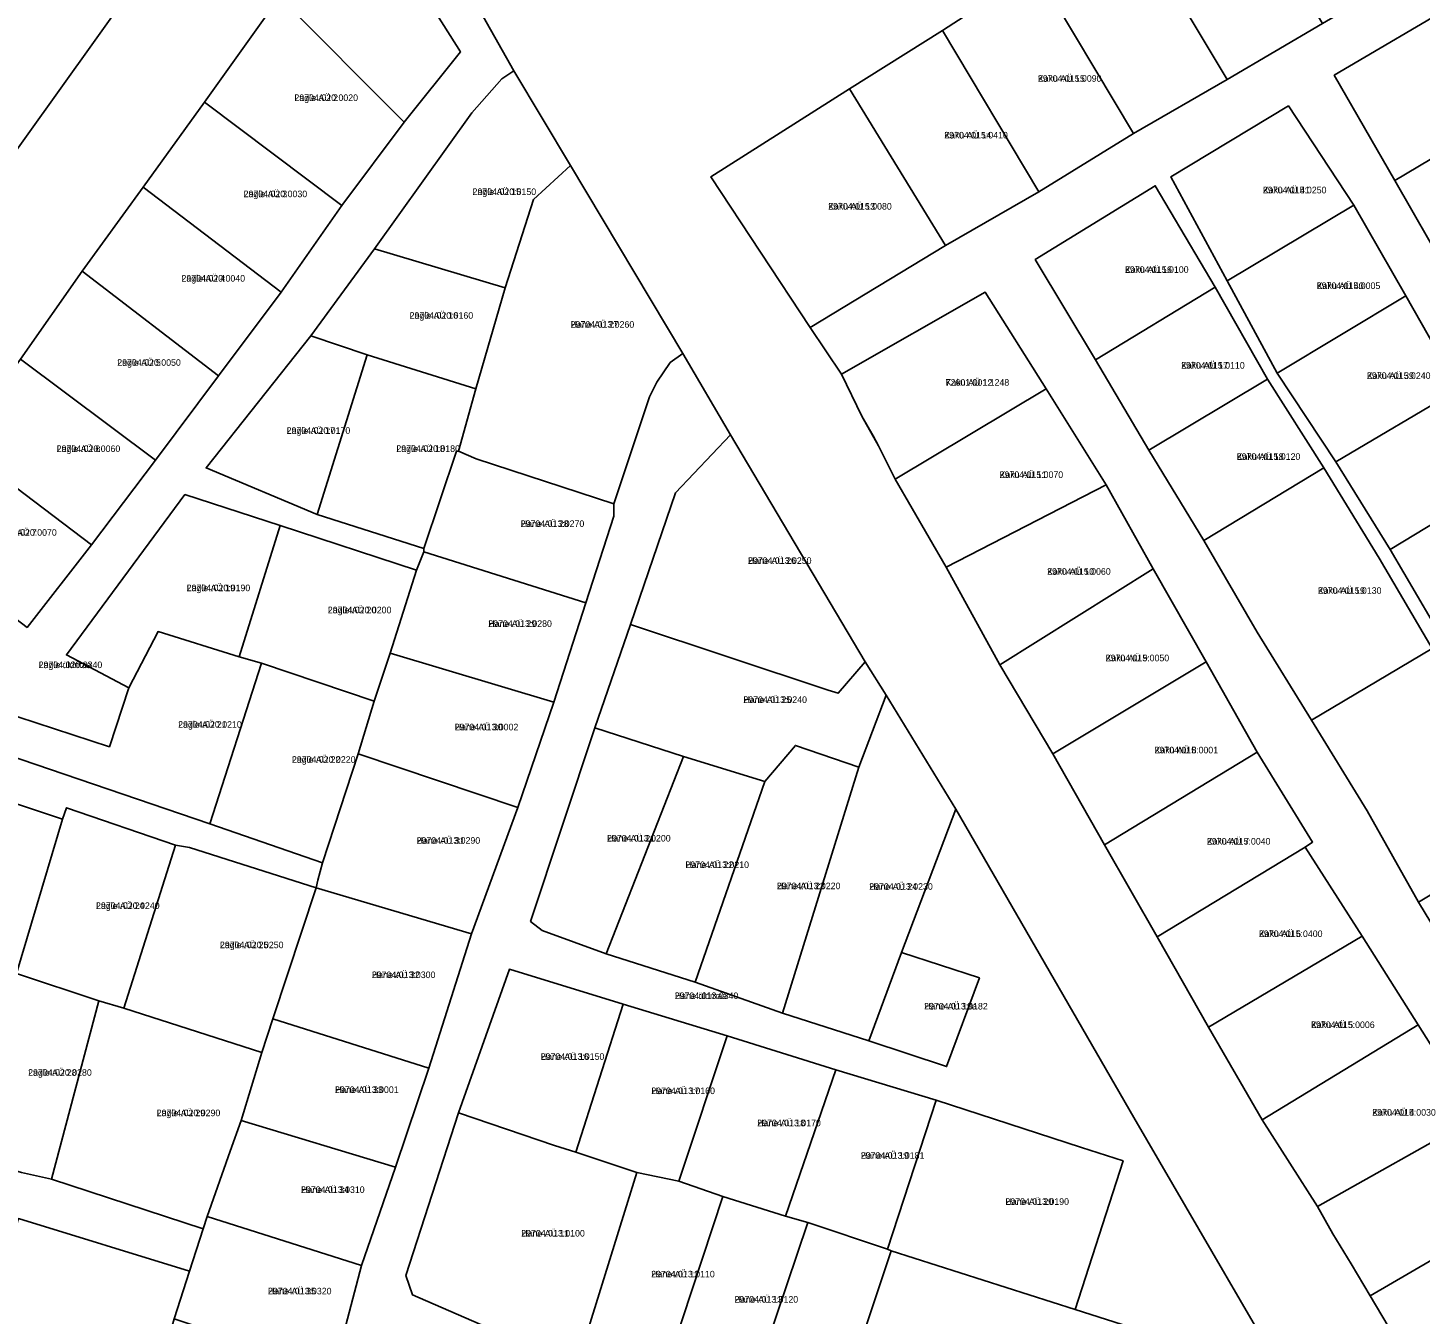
# Model space of a CAD drawing. Extents: x 504287 to 537970, y 6539941 to 6586214.
# Drawn here: x 515960.8 to 516278.4, y 6563495.5 to 6563788.8 of the extents above; entities that cross this region are included whole.
import ezdxf

# ---------------------------------------------------------------- set-up
doc = ezdxf.new("R2010")
doc.units = 0
for name, color, linetype in [('L_AADRESS', 7, 'Continuous'), ('PIIR', 7, 'Continuous'), ('TUNNUS', 7, 'Continuous')]:
    doc.layers.add(name, color=color, linetype=linetype)

msp = doc.modelspace()

# ---------------------------------------------------------------- linework, layer by layer
at = {"layer": 'PIIR'}
for points in [[(515624.14, 6564381.9), (516044.6, 6563895.65), (516050.16, 6563889.17), (516032.13, 6563864.26), (515943.97, 6563741.18), (515878.4, 6563653.75), (515772.68, 6563516.57), (515329.04, 6563669.28)], [(516382.23, 6563956.06), (516107.14, 6563904.56), (516093.47, 6563896.02), (516055.87, 6563846.69), (516051.44, 6563840.47), (516043.4, 6563829.17), (516042.96, 6563829.96), (516035.97, 6563820.5), (516018.23, 6563795.91), (516001.13, 6563771.83), (515987.14, 6563752.45), (515973.16, 6563733.29), (515959.13, 6563713.26), (515944.96, 6563693.9), (515930.89, 6563674.75), (515916.74, 6563654.55), (515902.87, 6563635.03), (515888.99, 6563615.59), (515875.08, 6563595.79), (515861.15, 6563576.25), (515846.5, 6563556.45), (515821.87, 6563521.4), (515802.3, 6563490.1)], [(516307.05, 6563434), (516278.14, 6563426.87), (516269.58, 6563442.63), (516255.07, 6563468.13), (516213.07, 6563540.34), (516172.49, 6563610.65), (516156.56, 6563636.66), (516151.81, 6563644.25), (516121.05, 6563696.02), (516110.18, 6563714.54), (516084.59, 6563757.41), (516071.68, 6563779), (516043.4, 6563829.17), (516051.44, 6563840.47), (516055.87, 6563846.69), (516093.47, 6563896.02), (516107.14, 6563904.56), (516382.23, 6563956.06)], [(515390.18, 6563134.77), (515513.06, 6563223.93), (515517.32, 6563222.54), (515623.22, 6563303.66), (515629.16, 6563314.21), (515772.68, 6563516.57), (515878.4, 6563653.75), (515943.97, 6563741.18), (516032.13, 6563864.26), (516050.16, 6563889.17), (516072.01, 6563919.38), (516096.09, 6563933.02), (516139.77, 6563941.2)], [(516043.4, 6563829.17), (516071.68, 6563779), (516068.93, 6563777.15), (516062.06, 6563769.44), (516039.88, 6563738.44), (516025.32, 6563718.6), (516001.47, 6563688.44), (516026.76, 6563677.87), (516051.1, 6563670.08), (516051.09, 6563669.35), (516049.46, 6563665.12), (516018.39, 6563675.31), (515996.62, 6563682.38), (515969.62, 6563645.82), (515983.87, 6563638.33), (515979.4, 6563624.88), (515958.5, 6563631.73)], [(515960.64, 6563652.08), (515975.36, 6563670.9), (515989.94, 6563690.19), (516004.27, 6563709.42), (516018.61, 6563728.55), (516032.42, 6563748.32), (516046.67, 6563767.31), (516059.45, 6563783.34), (516035.97, 6563820.5)], [(516291.18, 6563540.41), (516277.92, 6563561.48), (516265.12, 6563581.68), (516252.13, 6563602.02), (516253.84, 6563603.15), (516241.21, 6563623.62), (516229.52, 6563644.23), (516217.46, 6563665.44), (516206.77, 6563684.62), (516193.07, 6563706.46), (516179.15, 6563728.51), (516146.36, 6563709.85), (516139.22, 6563720.44), (516170.11, 6563739.15), (516191.42, 6563751.39), (516212.95, 6563764.7), (516234.37, 6563777.02), (516256.06, 6563789.77), (516283.8, 6563805.96)], [(516190.7, 6563802.01), (516169.41, 6563788.23), (516148.23, 6563774.88), (516116.57, 6563754.83), (516139.22, 6563720.44), (516146.36, 6563709.85), (516151.05, 6563700.28), (516154.83, 6563693.5), (516158.62, 6563685.89), (516170.29, 6563665.86), (516182.49, 6563643.55), (516194.6, 6563623.29), (516206.39, 6563602.51), (516218.36, 6563581.51), (516230.12, 6563560.96), (516242.32, 6563539.8), (516254.94, 6563520.03), (516258.46, 6563513.85), (516262.63, 6563507), (516266.92, 6563499.65), (516279.74, 6563478.18)], [(516287.98, 6563795.25), (516258.77, 6563777.98), (516272.57, 6563754.02), (516284.51, 6563733.19)], [(516287.14, 6563706.42), (516275.07, 6563727.69), (516263.26, 6563748.39), (516248.32, 6563771), (516221.47, 6563754.82), (516234.33, 6563731.13), (516245.73, 6563710.1), (516259.16, 6563689.81), (516271.52, 6563669.85), (516284, 6563648.59)], [(516281.08, 6563647.25), (516268.98, 6563667.87), (516256.42, 6563688.48), (516243.52, 6563708.71), (516231.62, 6563729.65), (516217.93, 6563752.79), (516190.58, 6563735.95), (516204.34, 6563713.08), (516216.45, 6563692.53), (516228.99, 6563671.89), (516241.17, 6563651.02), (516253.55, 6563630.97), (516266.25, 6563610.24), (516278, 6563589.47), (516290.52, 6563568.76)], [(516030.55, 6563482.28), (516036.91, 6563506.6), (516044.68, 6563529.02), (516052.27, 6563551.56), (516062, 6563582.26), (516072.55, 6563611), (516080.79, 6563635.08), (516088.1, 6563657.68), (516094.47, 6563677.43), (516094.45, 6563680.26), (516102.6, 6563704.63), (516104.3, 6563708.01), (516107.32, 6563712.53), (516110.18, 6563714.54), (516121.05, 6563696.02), (516108.55, 6563682.8), (516098.29, 6563652.78), (516090.15, 6563629.16), (516075.46, 6563585.06), (516078.09, 6563583.01), (516092.68, 6563577.69), (516112.98, 6563571.22), (516132.92, 6563564.13), (516152.64, 6563557.81), (516170.35, 6563551.97), (516177.83, 6563572.17), (516160.09, 6563577.97), (516172.49, 6563610.65), (516213.07, 6563540.34), (516255.07, 6563468.13)], [(515952.55, 6563624.24), (516002.29, 6563607.29), (516028.01, 6563598.42), (516026.94, 6563594.44), (516026.57, 6563592.7), (515997.66, 6563601.89), (515994.51, 6563602.41), (515969.59, 6563610.97), (515968.68, 6563608.38), (515946.91, 6563615.59)], [(515959.37, 6563527.77), (515966.18, 6563526.28), (516000.79, 6563514.99), (515997.65, 6563505.28), (515958.64, 6563517.28)]]:
    msp.add_lwpolyline(points, dxfattribs=at)
for points in [[(516233.36, 6563827.36), (516256.06, 6563789.77), (516234.37, 6563777.02), (516211.2, 6563815.61)], [(516035.97, 6563820.5), (516059.45, 6563783.34), (516046.67, 6563767.31), (516018.23, 6563795.91)], [(516190.7, 6563802.01), (516211.2, 6563815.61), (516234.37, 6563777.02), (516212.95, 6563764.7)], [(516169.41, 6563788.23), (516190.7, 6563802.01), (516212.95, 6563764.7), (516191.42, 6563751.39)], [(516018.23, 6563795.91), (516046.67, 6563767.31), (516032.42, 6563748.32), (516001.13, 6563771.83)], [(516258.77, 6563777.98), (516287.98, 6563795.25), (516289.62, 6563796.11), (516303.02, 6563772.71), (516302, 6563771.5), (516272.57, 6563754.02)], [(516148.23, 6563774.88), (516169.41, 6563788.23), (516191.42, 6563751.39), (516170.11, 6563739.15)], [(516062.06, 6563769.44), (516068.93, 6563777.15), (516071.68, 6563779), (516084.59, 6563757.41), (516076.13, 6563749.68), (516069.64, 6563729.49), (516039.88, 6563738.44)], [(516116.57, 6563754.83), (516148.23, 6563774.88), (516170.11, 6563739.15), (516139.22, 6563720.44)], [(516001.13, 6563771.83), (516032.42, 6563748.32), (516018.61, 6563728.55), (515987.14, 6563752.45)], [(516221.47, 6563754.82), (516248.32, 6563771), (516263.26, 6563748.39), (516234.33, 6563731.13)], [(516272.57, 6563754.02), (516302, 6563771.5), (516303.02, 6563772.71), (516314.35, 6563754.5), (516315.84, 6563751.99), (516284.51, 6563733.19)], [(516059.05, 6563692.29), (516062.97, 6563706.5), (516069.64, 6563729.49), (516076.13, 6563749.68), (516084.59, 6563757.41), (516110.18, 6563714.54), (516107.32, 6563712.53), (516104.3, 6563708.01), (516102.6, 6563704.63), (516094.45, 6563680.26), (516063.02, 6563690.51)], [(515987.14, 6563752.45), (516018.61, 6563728.55), (516004.27, 6563709.42), (515973.16, 6563733.29)], [(516190.58, 6563735.95), (516217.93, 6563752.79), (516231.62, 6563729.65), (516204.34, 6563713.08)], [(516263.26, 6563748.39), (516275.07, 6563727.69), (516245.73, 6563710.1), (516234.33, 6563731.13)], [(516025.32, 6563718.6), (516039.88, 6563738.44), (516069.64, 6563729.49), (516062.97, 6563706.5), (516038.21, 6563714.23)], [(515973.16, 6563733.29), (516004.27, 6563709.42), (515989.94, 6563690.19), (515959.13, 6563713.26)], [(516204.34, 6563713.08), (516231.62, 6563729.65), (516243.52, 6563708.71), (516216.45, 6563692.53)], [(516179.15, 6563728.51), (516193.07, 6563706.46), (516158.62, 6563685.89), (516154.83, 6563693.5), (516153.57, 6563695.77), (516151.05, 6563700.28), (516146.36, 6563709.85)], [(516245.73, 6563710.1), (516275.07, 6563727.69), (516287.14, 6563706.42), (516259.16, 6563689.81)], [(516025.32, 6563718.6), (516038.21, 6563714.23), (516026.76, 6563677.87), (516001.47, 6563688.44)], [(516038.21, 6563714.23), (516062.97, 6563706.5), (516059.05, 6563692.29), (516058.61, 6563692.27), (516051.1, 6563670.08), (516026.76, 6563677.87)], [(515959.13, 6563713.26), (515989.94, 6563690.19), (515975.36, 6563670.9), (515944.96, 6563693.9)], [(516216.45, 6563692.53), (516243.52, 6563708.71), (516256.42, 6563688.48), (516228.99, 6563671.89)], [(516158.62, 6563685.89), (516193.07, 6563706.46), (516206.77, 6563684.62), (516170.29, 6563665.86)], [(516259.16, 6563689.81), (516287.14, 6563706.42), (516299.3, 6563686.62), (516271.52, 6563669.85)], [(516108.55, 6563682.8), (516121.05, 6563696.02), (516151.81, 6563644.25), (516145.65, 6563637.08), (516143.31, 6563637.8), (516098.29, 6563652.78)], [(515944.96, 6563693.9), (515975.36, 6563670.9), (515960.64, 6563652.08), (515930.89, 6563674.75)], [(516051.1, 6563670.08), (516058.61, 6563692.27), (516059.05, 6563692.29), (516063.02, 6563690.51), (516094.45, 6563680.26), (516094.47, 6563677.43), (516088.1, 6563657.68), (516051.09, 6563669.35)], [(516241.17, 6563651.02), (516228.99, 6563671.89), (516256.42, 6563688.48), (516268.98, 6563667.87), (516281.08, 6563647.25), (516253.55, 6563630.97)], [(516271.52, 6563669.85), (516299.3, 6563686.62), (516310.28, 6563663.95), (516284, 6563648.59)], [(515983.87, 6563638.33), (515969.62, 6563645.82), (515996.62, 6563682.38), (516018.39, 6563675.31), (516009.04, 6563645.4), (515990.5, 6563651.13)], [(516170.29, 6563665.86), (516206.77, 6563684.62), (516217.46, 6563665.44), (516182.49, 6563643.55)], [(516009.04, 6563645.4), (516018.39, 6563675.31), (516049.46, 6563665.12), (516043.42, 6563646.24), (516039.78, 6563635.31), (516014.09, 6563643.94)], [(516049.46, 6563665.12), (516051.09, 6563669.35), (516088.1, 6563657.68), (516080.79, 6563635.08), (516043.42, 6563646.24)], [(516182.49, 6563643.55), (516217.46, 6563665.44), (516229.52, 6563644.23), (516194.6, 6563623.29)], [(515958.5, 6563631.73), (515979.4, 6563624.88), (515983.87, 6563638.33), (515990.5, 6563651.13), (516009.04, 6563645.4), (516014.09, 6563643.94), (516002.29, 6563607.29), (515952.55, 6563624.24)], [(516090.15, 6563629.16), (516098.29, 6563652.78), (516143.31, 6563637.8), (516145.65, 6563637.08), (516151.81, 6563644.25), (516156.56, 6563636.66), (516150.31, 6563620.23), (516135.86, 6563625.19), (516128.88, 6563616.95), (516110.36, 6563622.65)], [(516266.25, 6563610.24), (516253.55, 6563630.97), (516281.08, 6563647.25), (516293.66, 6563626.75), (516306.16, 6563606.35), (516278, 6563589.47)], [(516014.09, 6563643.94), (516039.78, 6563635.31), (516036.13, 6563623.26), (516028.01, 6563598.42), (516002.29, 6563607.29)], [(516043.42, 6563646.24), (516080.79, 6563635.08), (516072.55, 6563611), (516036.13, 6563623.26), (516039.78, 6563635.31)], [(516194.6, 6563623.29), (516229.52, 6563644.23), (516241.21, 6563623.62), (516206.39, 6563602.51)], [(516150.31, 6563620.23), (516156.56, 6563636.66), (516172.49, 6563610.65), (516160.09, 6563577.97), (516152.64, 6563557.81), (516132.92, 6563564.13)], [(516075.46, 6563585.06), (516090.15, 6563629.16), (516110.36, 6563622.65), (516092.68, 6563577.69), (516078.09, 6563583.01)], [(516128.88, 6563616.95), (516135.86, 6563625.19), (516150.31, 6563620.23), (516132.92, 6563564.13), (516112.98, 6563571.22)], [(516026.94, 6563594.44), (516028.01, 6563598.42), (516036.13, 6563623.26), (516072.55, 6563611), (516062, 6563582.26), (516026.57, 6563592.7)], [(516110.36, 6563622.65), (516128.88, 6563616.95), (516112.98, 6563571.22), (516092.68, 6563577.69)], [(516206.39, 6563602.51), (516241.21, 6563623.62), (516253.84, 6563603.15), (516252.13, 6563602.02), (516218.36, 6563581.51)], [(515923.08, 6563585.49), (515946.91, 6563615.59), (515968.68, 6563608.38), (515958.2, 6563573.15), (515939.24, 6563579.91)], [(515968.68, 6563608.38), (515969.59, 6563610.97), (515994.51, 6563602.41), (515982.67, 6563565.25), (515977, 6563566.92), (515958.2, 6563573.15)], [(516306.16, 6563606.35), (516319.18, 6563586.25), (516290.52, 6563568.76), (516278, 6563589.47)], [(515994.51, 6563602.41), (515997.66, 6563601.89), (516026.57, 6563592.7), (516016.69, 6563562.86), (516014.21, 6563555.15), (515982.67, 6563565.25)], [(516218.36, 6563581.51), (516252.13, 6563602.02), (516265.12, 6563581.68), (516230.12, 6563560.96)], [(516026.57, 6563592.7), (516062, 6563582.26), (516052.27, 6563551.56), (516016.69, 6563562.86)], [(516230.12, 6563560.96), (516265.12, 6563581.68), (516277.92, 6563561.48), (516242.32, 6563539.8)], [(516160.09, 6563577.97), (516177.83, 6563572.17), (516170.35, 6563551.97), (516152.64, 6563557.81)], [(516096.55, 6563566.22), (516070.66, 6563574.15), (516059.04, 6563541.39), (516046.98, 6563504.34), (516048.51, 6563499.93), (516067.27, 6563491.8), (516086.59, 6563485.69), (516105.29, 6563479.92), (516124.41, 6563474), (516143.63, 6563467.82), (516144.6, 6563470.66), (516182.24, 6563458.88), (516225.44, 6563447.4), (516237.06, 6563484.66), (516199.68, 6563496.54), (516210.62, 6563530.45), (516201.11, 6563533.5), (516167.94, 6563544.31), (516145.06, 6563551.22), (516120.27, 6563558.99)], [(516070.66, 6563574.15), (516096.55, 6563566.22), (516085.76, 6563532.41), (516080.94, 6563533.94), (516059.04, 6563541.39)], [(515958.2, 6563573.15), (515977, 6563566.92), (515966.18, 6563526.28), (515959.37, 6563527.77), (515944.75, 6563532.12)], [(515977, 6563566.92), (515982.67, 6563565.25), (516014.21, 6563555.15), (516009.43, 6563539.68), (516006.95, 6563532.65), (516001.68, 6563517.74), (516000.79, 6563514.99), (515966.18, 6563526.28)], [(516085.76, 6563532.41), (516096.55, 6563566.22), (516120.27, 6563558.99), (516109.28, 6563525.85), (516099.71, 6563527.77)], [(516016.69, 6563562.86), (516052.27, 6563551.56), (516044.68, 6563529.02), (516009.43, 6563539.68), (516014.21, 6563555.15)], [(516242.32, 6563539.8), (516277.92, 6563561.48), (516291.18, 6563540.41), (516254.94, 6563520.03)], [(516109.28, 6563525.85), (516120.27, 6563558.99), (516145.06, 6563551.22), (516133.63, 6563517.83), (516119.34, 6563522.35)], [(516133.63, 6563517.83), (516145.06, 6563551.22), (516167.94, 6563544.31), (516156.85, 6563510.34), (516138.72, 6563516.39)], [(516156.85, 6563510.34), (516167.94, 6563544.31), (516201.11, 6563533.5), (516210.62, 6563530.45), (516199.68, 6563496.54), (516157.7, 6563509.92)], [(516006.95, 6563532.65), (516009.43, 6563539.68), (516044.68, 6563529.02), (516036.91, 6563506.6), (516001.68, 6563517.74)], [(516067.27, 6563491.8), (516048.51, 6563499.93), (516046.98, 6563504.34), (516059.04, 6563541.39), (516080.94, 6563533.94), (516085.76, 6563532.41), (516099.71, 6563527.77), (516086.59, 6563485.69)], [(516266.92, 6563499.65), (516262.63, 6563507), (516258.46, 6563513.85), (516254.94, 6563520.03), (516291.18, 6563540.41), (516304.08, 6563521.24)], [(516099.71, 6563527.77), (516109.28, 6563525.85), (516119.34, 6563522.35), (516105.29, 6563479.92), (516086.59, 6563485.69)], [(516119.34, 6563522.35), (516133.63, 6563517.83), (516138.72, 6563516.39), (516124.41, 6563474), (516105.29, 6563479.92)], [(516266.92, 6563499.65), (516304.08, 6563521.24), (516317.32, 6563500.77), (516279.74, 6563478.18)], [(515945.37, 6563475.29), (515958.64, 6563517.28), (515997.65, 6563505.28), (515994.15, 6563494.47), (515983.62, 6563457.73), (515945.71, 6563469.61)], [(515997.65, 6563505.28), (516000.79, 6563514.99), (516001.68, 6563517.74), (516036.91, 6563506.6), (516030.55, 6563482.28), (515994.15, 6563494.47)], [(516138.72, 6563516.39), (516156.85, 6563510.34), (516157.7, 6563509.92), (516144.6, 6563470.66), (516143.63, 6563467.82), (516124.41, 6563474)], [(516144.6, 6563470.66), (516157.7, 6563509.92), (516199.68, 6563496.54), (516237.06, 6563484.66), (516225.44, 6563447.4), (516182.24, 6563458.88)]]:
    msp.add_lwpolyline(points, close=True, dxfattribs=at)

# ---------------------------------------------------------------- texts
at = {"layer": 'L_AADRESS'}
for s, p in [('Kaku AÜ 15', (516191.18, 6563776.5)), ('Lagle AÜ 2', (516021.61, 6563772.12)), ('Kaku AÜ 14', (516169.82, 6563763.58)), ('Lagle AÜ 3', (516010.02, 6563750.19)), ('Lagle AÜ 15', (516062.24, 6563750.68)), ('Kaku AÜ 41', (516242.5, 6563751.07)), ('Kaku AÜ 13', (516143.34, 6563747.36)), ('Lagle AÜ 4', (515995.85, 6563730.94)), ('Kaku AÜ 16', (516211.04, 6563732.93)), ('Kaku AÜ 40', (516254.77, 6563729.25)), ('Lagle AÜ 16', (516047.88, 6563722.47)), ('Hane AÜ 27', (516084.61, 6563720.42)), ('Lagle AÜ 5', (515981.2, 6563711.74)), ('Kaku AÜ 17', (516223.84, 6563711.09)), ('Kaku AÜ 39', (516266.22, 6563708.75)), ('Kaku AÜ 12', (516170.13, 6563707.2)), ('Lagle AÜ 17', (516019.84, 6563696.22)), ('Lagle AÜ 6', (515967.39, 6563692.08)), ('Lagle AÜ 18', (516044.86, 6563692.11)), ('Kaku AÜ 18', (516236.53, 6563690.3)), ('Kaku AÜ 11', (516182.44, 6563686.16)), ('Hane AÜ 28', (516073.22, 6563674.99)), ('Lagle AÜ 7', (515952.9, 6563672.99)), ('Hane AÜ 26', (516125.05, 6563666.58)), ('Kaku AÜ 10', (516193.28, 6563664.09)), ('Lagle AÜ 19', (515997.03, 6563660.35)), ('Kaku AÜ 19', (516255.04, 6563659.75)), ('Lagle AÜ 20', (516029.23, 6563655.31)), ('Hane AÜ 29', (516065.83, 6563652.21)), ('Lagle üldmaa', (515963.28, 6563642.81)), ('Kaku AÜ 9', (516206.62, 6563644.37)), ('Hane AÜ 25', (516124, 6563634.87)), ('Lagle AÜ 21', (515995.09, 6563629.21)), ('Hane AÜ 30', (516058.17, 6563628.62)), ('Kaku AÜ 8', (516217.77, 6563623.37)), ('Lagle AÜ 22', (516021.04, 6563621.22)), ('Hane AÜ 31', (516049.48, 6563602.76)), ('Hane AÜ 21', (516092.91, 6563603.27)), ('Kaku AÜ 7', (516229.72, 6563602.57)), ('Hane AÜ 22', (516110.78, 6563597.22)), ('Hane AÜ 23', (516131.64, 6563592.4)), ('Hane AÜ 24', (516152.71, 6563592.26)), ('Lagle AÜ 24', (515976.36, 6563587.89)), ('Lagle AÜ 25', (516004.62, 6563578.95)), ('Kaku AÜ 6', (516241.59, 6563581.49)), ('Hane AÜ 32', (516039.27, 6563572.13)), ('Hane üldmaa', (516108.36, 6563567.35)), ('Hane AÜ 19a', (516165.23, 6563564.97)), ('Kaku AÜ 5', (516253.48, 6563560.74)), ('Hane AÜ 16', (516077.79, 6563553.49)), ('Lagle AÜ 28', (515960.88, 6563549.85)), ('Hane AÜ 33', (516030.87, 6563545.94)), ('Hane AÜ 17', (516103.02, 6563545.68)), ('Lagle AÜ 29', (515990.2, 6563540.64)), ('Kaku AÜ 4', (516267.43, 6563540.76)), ('Hane AÜ 18', (516127.17, 6563538.35)), ('Hane AÜ 19', (516150.79, 6563530.93)), ('Hane AÜ 34', (516023.12, 6563523.14)), ('Hane AÜ 20', (516183.76, 6563520.42)), ('Hane AÜ 11', (516073.34, 6563513.2)), ('Hane AÜ 12', (516102.97, 6563503.88)), ('Hane AÜ 35', (516015.57, 6563500.01)), ('Hane AÜ 13', (516122, 6563498.13))]:
    msp.add_text(s, height=1.5, dxfattribs=at).set_placement(p)
at = {"layer": 'TUNNUS'}
for s, p in [('29704:015:0090', (516191.18, 6563776.5)), ('29704:020:0020', (516021.61, 6563772.12)), ('29704:015:0410', (516169.82, 6563763.58)), ('29704:020:0030', (516010.02, 6563750.19)), ('29704:020:0150', (516062.24, 6563750.68)), ('29704:015:0250', (516242.5, 6563751.07)), ('29704:015:0080', (516143.34, 6563747.36)), ('29704:015:0100', (516211.04, 6563732.93)), ('29704:020:0040', (515995.85, 6563730.94)), ('29704:015:0005', (516254.77, 6563729.25)), ('29704:020:0160', (516047.88, 6563722.47)), ('29704:013:0260', (516084.61, 6563720.42)), ('29704:020:0050', (515981.2, 6563711.74)), ('29704:015:0110', (516223.84, 6563711.09)), ('72601:001:1248', (516170.13, 6563707.2)), ('29704:015:0240', (516266.22, 6563708.75)), ('29704:020:0170', (516019.84, 6563696.22)), ('29704:020:0060', (515967.39, 6563692.08)), ('29704:020:0180', (516044.86, 6563692.11)), ('29704:015:0120', (516236.53, 6563690.3)), ('29704:015:0070', (516182.44, 6563686.16)), ('29704:013:0270', (516073.22, 6563674.99)), ('29704:020:0070', (515952.9, 6563672.99)), ('29704:013:0250', (516125.05, 6563666.58)), ('29704:015:0060', (516193.28, 6563664.09)), ('29704:020:0190', (515997.03, 6563660.35)), ('29704:015:0130', (516255.04, 6563659.75)), ('29704:020:0200', (516029.23, 6563655.31)), ('29704:013:0280', (516065.83, 6563652.21)), ('29704:020:0340', (515963.28, 6563642.81)), ('29704:015:0050', (516206.62, 6563644.37)), ('29704:013:0240', (516124, 6563634.87)), ('29704:020:0210', (515995.09, 6563629.21)), ('29704:013:0002', (516058.17, 6563628.62)), ('29704:015:0001', (516217.77, 6563623.37)), ('29704:020:0220', (516021.04, 6563621.22)), ('29704:013:0290', (516049.48, 6563602.76)), ('29704:013:0200', (516092.91, 6563603.27)), ('29704:015:0040', (516229.72, 6563602.57)), ('29704:013:0210', (516110.78, 6563597.22)), ('29704:013:0220', (516131.64, 6563592.4)), ('29704:013:0230', (516152.71, 6563592.26)), ('29704:020:0240', (515976.36, 6563587.89)), ('29704:020:0250', (516004.62, 6563578.95)), ('29704:015:0400', (516241.59, 6563581.49)), ('29704:013:0300', (516039.27, 6563572.13)), ('29704:013:0340', (516108.36, 6563567.35)), ('29704:013:0182', (516165.23, 6563564.97)), ('29704:015:0006', (516253.48, 6563560.74)), ('29704:013:0150', (516077.79, 6563553.49)), ('29704:020:0280', (515960.88, 6563549.85)), ('29704:013:0001', (516030.87, 6563545.94)), ('29704:013:0160', (516103.02, 6563545.68)), ('29704:020:0290', (515990.2, 6563540.64)), ('29704:015:0030', (516267.43, 6563540.76)), ('29704:013:0170', (516127.17, 6563538.35)), ('29704:013:0181', (516150.79, 6563530.93)), ('29704:013:0310', (516023.12, 6563523.14)), ('29704:013:0190', (516183.76, 6563520.42)), ('29704:013:0100', (516073.34, 6563513.2)), ('29704:013:0110', (516102.97, 6563503.88)), ('29704:013:0320', (516015.57, 6563500.01)), ('29704:013:0120', (516122, 6563498.13))]:
    msp.add_text(s, height=1.5, dxfattribs=at).set_placement(p)

doc.saveas('drawing.dxf')
